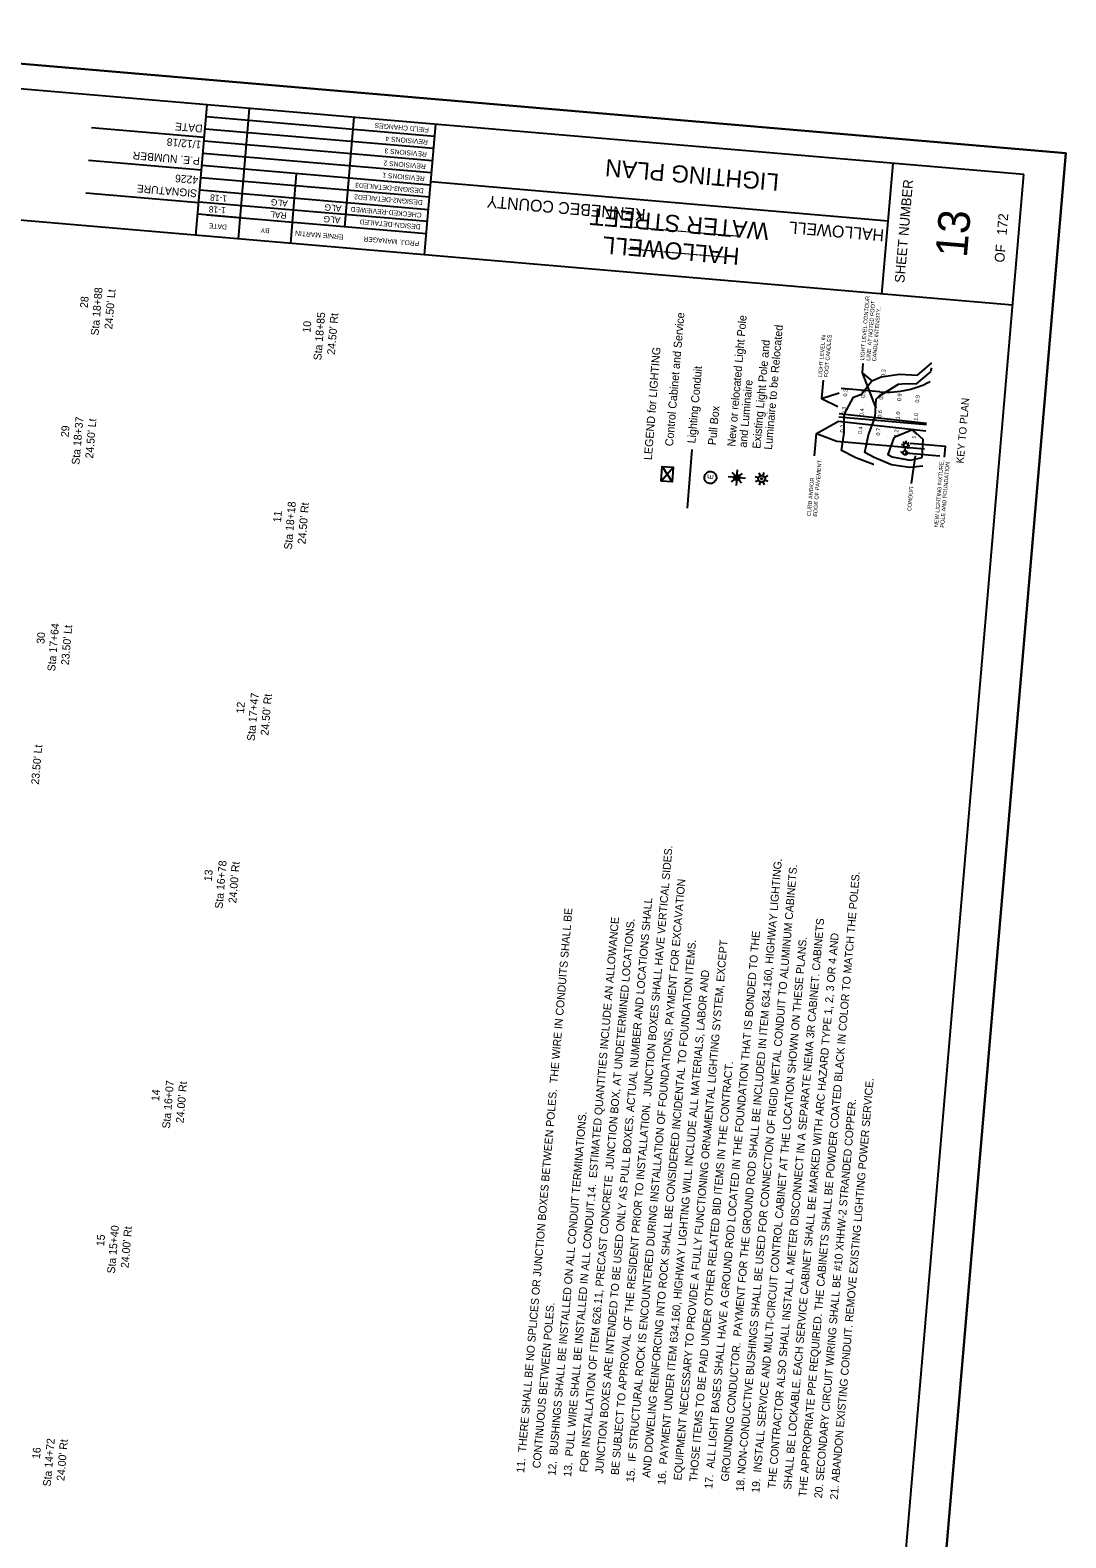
# Model space of a CAD drawing. Extents: x 1137099 to 1137719, y 529062 to 529956.
# Drawn here: x 1137324 to 1137719, y 529381 to 529956 of the extents above; entities that cross this region are included whole.
import ezdxf

# ---------------------------------------------------------------- set-up
doc = ezdxf.new("R2010")
doc.units = 0
for name, color, linetype in [('ANNOTATION', 7, 'Continuous'), ('BORDER', 7, 'Continuous'), ('BRIDGE_TITLE', 7, 'Continuous'), ('D_LIGHTING', 7, 'Continuous'), ('D_Lighting_Text', 7, 'Continuous'), ('D_Utilities_Pole_StreetLight', 7, 'Continuous'), ('HIGHWAY_TITLE', 7, 'Continuous'), ('Liting Text', 7, 'Continuous'), ('PLOT BOUNDARY', 7, 'Continuous'), ('UTILS GRND', 7, 'Continuous')]:
    doc.layers.add(name, color=color, linetype=linetype)

msp = doc.modelspace()

# ---------------------------------------------------------------- linework, layer by layer
at = {"layer": 'ANNOTATION'}
for p, q in [((1137641.47, 529825.05), (1137646.62, 529811.52)), ((1137625.94, 529815.24), (1137632.65, 529817.34)), ((1137648.23, 529817.78), (1137633.51, 529819.04)), ((1137665.97, 529805.2), (1137632.56, 529808.07)), ((1137666.01, 529805.64), (1137632.67, 529809.37)), ((1137632.44, 529806.62), (1137665.77, 529802.89)), ((1137624.04, 529801.85), (1137631.77, 529798.92)), ((1137631.77, 529798.92), (1137665.18, 529796.06)), ((1137656.55, 529797.67), (1137656.56, 529797.72)), ((1137659.29, 529797.44), (1137659.3, 529797.49)), ((1137656.31, 529794.93), (1137656.32, 529794.98)), ((1137657.45, 529794.06), (1137657.45, 529794.06)), ((1137657.48, 529794.41), (1137657.48, 529794.41)), ((1137657.79, 529794.03), (1137657.79, 529794.03)), ((1137657.82, 529794.38), (1137657.82, 529794.38)), ((1137660.28, 529782.77), (1137661.82, 529793.4))]:
    msp.add_line(p, q, dxfattribs=at)
msp.add_lwpolyline([(1137098.65, 529108.8), (1137171.14, 529955.71), (1137719.13, 529908.81), (1137646.65, 529061.9)], close=True, dxfattribs=at)
for points in [[(1137645.97, 529790.05), (1137645.76, 529790.1), (1137639.08, 529792.65), (1137633.62, 529795.36), (1137634.63, 529802.18), (1137634.63, 529809.09), (1137638.11, 529815.7), (1137641.17, 529816.85), (1137645.12, 529822.01), (1137648.66, 529823.51), (1137655.65, 529824.46), (1137662.53, 529824.12), (1137666.07, 529827.13), (1137668.01, 529828.76)], [(1137641.77, 529828.55), (1137641.47, 529825.05), (1137645.12, 529822.01)], [(1137664.6, 529789.47), (1137659.48, 529788.96), (1137652.65, 529789.89), (1137645.99, 529792.77), (1137642.55, 529794.59), (1137643.86, 529801.39), (1137646.4, 529808.08), (1137646.85, 529814.95), (1137648.03, 529816.26), (1137655.32, 529820.72), (1137658.05, 529820.9), (1137662.24, 529820.84), (1137667.73, 529825.49)], [(1137626.55, 529822.24), (1137625.94, 529815.24), (1137632.24, 529812.13)], [(1137623.3, 529793.37), (1137624.04, 529801.85), (1137632.44, 529806.62)], [(1137664.3, 529792.73), (1137664.79, 529799.59), (1137660.72, 529803.3), (1137653.92, 529800.53), (1137653.54, 529800.17), (1137651.23, 529793.85), (1137652.92, 529792.94), (1137659.72, 529791.68), (1137664.3, 529792.73)], [(1137672.86, 529792.83), (1137673.21, 529796.89), (1137659.75, 529798.04)]]:
    msp.add_lwpolyline(points, dxfattribs=at)
for centre, major_axis, start_param, end_param in [((1137669.03, 529826.16), (0.89, 1.05), 1.737973, 2.633498), ((1137651.2, 529852.08), (22.21, 26.32), 4.064294, 4.213502), ((1137651.2, 529852.08), (22.21, 26.32), 4.213502, 4.323837), ((1137651.2, 529852.08), (22.21, 26.32), 4.323837, 4.333024), ((1137651.2, 529852.08), (22.21, 26.32), 3.756531, 4.064294)]:
    msp.add_ellipse(centre, major_axis=major_axis, ratio=0.998974, start_param=start_param, end_param=end_param, dxfattribs=at)
at = {"layer": 'BORDER'}
for p, q in [((1137703.07, 529900.61), (1137179.98, 529945.38)), ((1137387.44, 529877.44), (1137391.7, 529927.26)), ((1137390.64, 529914.81), (1137347.56, 529918.49)), ((1137474.62, 529869.98), (1137478.89, 529919.8)), ((1137389.57, 529902.35), (1137346.49, 529906.04)), ((1137634.86, 529103.53), (1137703.08, 529900.61)), ((1137648.98, 529855.06), (1137653.25, 529904.88)), ((1137698.8, 529850.79), (1137175.72, 529895.56)), ((1137651.37, 529882.91), (1137477.01, 529897.83)), ((1137388.51, 529889.9), (1137345.43, 529893.58))]:
    msp.add_line(p, q, dxfattribs=at)
for points in [[(1137403.63, 529876.06), (1137407.9, 529925.88)], [(1137478.08, 529910.52), (1137390.91, 529917.98)], [(1137478.47, 529915.16), (1137391.31, 529922.62)], [(1137444.17, 529880.69), (1137447.75, 529922.46)], [(1137477.68, 529905.88), (1137390.51, 529913.34)], [(1137477.28, 529901.24), (1137390.12, 529908.7)], [(1137476.88, 529896.6), (1137389.72, 529904.06)], [(1137424.25, 529882.4), (1137425.84, 529900.96)], [(1137388.92, 529894.78), (1137476.09, 529887.32)], [(1137476.49, 529891.96), (1137389.32, 529899.42)], [(1137475.69, 529882.67), (1137388.53, 529890.13)], [(1137404.32, 529884.1), (1137388.13, 529885.49)], [(1137475.3, 529878.03), (1137391.65, 529885.19)], [(1137423.56, 529874.35), (1137424.25, 529882.4)]]:
    msp.add_lwpolyline(points, dxfattribs=at)
at = {"layer": 'D_LIGHTING'}
for p, q in [((1137564.85, 529783.68), (1137569.41, 529789.02)), ((1137565.2, 529789.29), (1137569.06, 529783.41)), ((1137593.68, 529785.04), (1137590.4, 529785.37)), ((1137593.68, 529785.04), (1137591.52, 529783.46)), ((1137593.68, 529785.04), (1137591.88, 529787.02)), ((1137593.68, 529785.04), (1137593.38, 529782.09)), ((1137593.68, 529785.04), (1137593.98, 529787.99)), ((1137593.68, 529785.04), (1137595.84, 529786.62)), ((1137596.96, 529784.7), (1137593.68, 529785.04)), ((1137593.68, 529785.04), (1137595.47, 529783.06)), ((1137600.73, 529785.45), (1137601.94, 529785.03)), ((1137602.04, 529786.91), (1137602.59, 529785.75)), ((1137604, 529787.01), (1137603.57, 529785.81)), ((1137605.46, 529785.7), (1137604.3, 529785.15)), ((1137600.83, 529783.5), (1137601.99, 529784.05)), ((1137602.29, 529782.19), (1137602.72, 529783.39)), ((1137604.25, 529782.29), (1137603.7, 529783.44)), ((1137604.35, 529784.17), (1137605.56, 529783.74))]:
    msp.add_line(p, q, dxfattribs=at)
msp.add_lwpolyline([(1137564.85, 529783.68), (1137565.2, 529789.29), (1137569.41, 529789.02), (1137569.06, 529783.41)], close=True, dxfattribs=at)
for radius in [1.28, 0.29]:
    msp.add_circle((1137603.15, 529784.6), radius, dxfattribs=at)
msp.add_ellipse((1137593.68, 529785.04), major_axis=(1.12, -0.11), ratio=0.899857, dxfattribs=at)
at = {"layer": 'D_Utilities_Pole_StreetLight'}
for p, q in [((1137657.32, 529797.52), (1137656.53, 529797.59)), ((1137657.5, 529796.93), (1137656.89, 529796.42)), ((1137657.61, 529798.06), (1137657.09, 529798.67)), ((1137657.93, 529795.34), (1137658.05, 529796.65)), ((1137658.19, 529798.24), (1137658.26, 529799.04)), ((1137658.63, 529796.83), (1137659.14, 529796.21)), ((1137658.73, 529797.96), (1137659.35, 529798.47)), ((1137658.92, 529797.37), (1137659.71, 529797.3)), ((1137657.04, 529794.6), (1137656.22, 529794.67)), ((1137658.67, 529794.45), (1137659.49, 529794.38))]:
    msp.add_line(p, q, dxfattribs=at)
for centre, major_axis in [((1137658.12, 529797.44), (-0.516, -0.612)), ((1137657.85, 529794.52), (0.529, 0.627))]:
    msp.add_ellipse(centre, major_axis=major_axis, ratio=0.998974, dxfattribs=at)
at = {"layer": 'Liting Text'}
for p, q in [((1137574.81, 529773.45), (1137576.71, 529795.73)), ((1137657.85, 529794.52), (1137671.07, 529793.39))]:
    msp.add_line(p, q, dxfattribs=at)
at = {"layer": 'PLOT BOUNDARY'}
msp.add_lwpolyline([(1137646.65, 529061.9), (1137719.13, 529908.81), (1137171.14, 529955.71), (1137098.65, 529108.8)], close=True, dxfattribs=at)
at = {"layer": 'UTILS GRND'}
msp.add_ellipse((1137583.58, 529785.08), major_axis=(-2.29, 0.32), ratio=0.999971, dxfattribs=at)

# ---------------------------------------------------------------- texts
at = {"layer": 'ANNOTATION'}
for s, height, rotation, p in [('LIGHT LEVEL CONTOUR', 1.528, 85.04728, (1137642.2, 529829.74)), ('LINE  AT NOTED FOOT', 1.528, 85.04728, (1137644.48, 529829.55)), ('CANDLE INTENSITY.', 1.528, 85.04728, (1137646.77, 529829.35)), ('LIGHT LEVEL IN', 1.528, 85.04728, (1137626.14, 529823.39)), ('FOOT CANDLES', 1.528, 85.04728, (1137628.42, 529823.2)), ('0.3', 1.528, 85.04728, (1137650.18, 529823.38)), ('0.3', 1.528, 85.04728, (1137635.72, 529815.91)), ('0.3', 1.528, 85.04728, (1137642.57, 529815.32)), ('0.6', 1.528, 85.04728, (1137649.43, 529814.73)), ('0.9', 1.528, 85.04728, (1137656.29, 529814.14)), ('0.9', 1.528, 85.04728, (1137663.15, 529813.56)), ('KEY TO PLAN', 2.8603, 85.04728, (1137680.17, 529790.35)), ('0.3', 1.528, 85.04728, (1137635.12, 529809.05)), ('0.4', 1.528, 85.04728, (1137641.98, 529808.46)), ('0.6', 1.528, 85.04728, (1137648.84, 529807.87)), ('1.0', 1.528, 85.04728, (1137655.69, 529807.28)), ('1.0', 1.528, 85.04728, (1137662.55, 529806.7)), ('0.3', 1.528, 85.04728, (1137634.53, 529802.19)), ('0.4', 1.528, 85.04728, (1137641.38, 529801.6)), ('0.7', 1.528, 85.04728, (1137648.24, 529801.01)), ('1.2', 1.528, 85.04728, (1137655.1, 529800.43)), ('1.4', 1.528, 85.04728, (1137661.96, 529799.84)), ('EDGE OF PAVEMENT.', 1.528, 85.04728, (1137624.19, 529770.08)), ('NEW LIGHTING FIXTURE,', 1.528, 85.04728, (1137670.41, 529766.12)), ('POLE AND FOUNDATION.', 1.528, 85.04728, (1137672.69, 529765.92)), ('CURB AND/OR', 1.528, 85.04728, (1137621.9, 529770.27)), ('CONDUIT', 1.528, 85.04728, (1137660.16, 529772.25)), ('  BE SUBJECT TO APPROVAL OF THE RESIDENT PRIOR TO INSTALLATION.  JUNCTION BOXES SHALL HAVE VERTICAL SIDES.', 3, 85.10821, (1137548.44, 529402.32)), ('   GROUNDING CONDUCTOR.  PAYMENT FOR THE GROUND ROD SHALL BE INCLUDED IN ITEM 634.160, HIGHWAY LIGHTING.', 3, 85.10821, (1137590.29, 529398.74)), ('18. NON-CONDUCTIVE BUSHINGS SHALL BE USED FOR CONNECTION OF RIGID METAL CONDUIT TO ALUMINUM CABINETS.', 3, 85.10821, (1137596.26, 529398.23)), ('15.  IF STRUCTURAL ROCK IS ENCOUNTERED DURING INSTALLATION OF FOUNDATIONS, PAYMENT FOR EXCAVATION ', 3, 85.10821, (1137554.42, 529401.81)), ('THE APPROPRIATE PPE REQUIRED. THE CABINETS SHALL BE POWDER COATED BLACK IN COLOR TO MATCH THE POLES.', 3, 85.10821, (1137620.18, 529396.18)), ('  JUNCTION BOXES ARE INTENDED TO BE USED ONLY AS PULL BOXES. ACTUAL NUMBER AND LOCATIONS SHALL ', 3, 85.10821, (1137542.46, 529402.83)), ('11.  THERE SHALL BE NO SPLICES OR JUNCTION BOXES BETWEEN POLES.  THE WIRE IN CONDUITS SHALL BE ', 3, 85.10821, (1137512.57, 529405.39)), ('13.  PULL WIRE SHALL BE INSTALLED IN ALL CONDUIT.14.  ESTIMATED QUANTITIES INCLUDE AN ALLOWANCE ', 3, 85.10821, (1137530.5, 529403.86)), ('  FOR INSTALLATION OF ITEM 626.11, PRECAST CONCRETE  JUNCTION BOX, AT UNDETERMINED LOCATIONS. ', 3, 85.10821, (1137536.48, 529403.34)), ('  THE CONTRACTOR ALSO SHALL INSTALL A METER DISCONNECT IN A SEPARATE NEMA 3R CABINET. CABINETS ', 3, 85.10821, (1137608.22, 529397.21)), ('  AND DOWELING REINFORCING INTO ROCK SHALL BE CONSIDERED INCIDENTAL TO FOUNDATION ITEMS.', 3, 85.10821, (1137560.39, 529401.3)), ('  EQUIPMENT NECESSARY TO PROVIDE A FULLY FUNCTIONING ORNAMENTAL LIGHTING SYSTEM, EXCEPT ', 3, 85.10821, (1137572.35, 529400.27)), ('17.  ALL LIGHT BASES SHALL HAVE A GROUND ROD LOCATED IN THE FOUNDATION THAT IS BONDED TO THE', 3, 85.10821, (1137584.31, 529399.25)), ('19.  INSTALL SERVICE AND MULTI-CIRCUIT CONTROL CABINET AT THE LOCATION SHOWN ON THESE PLANS.  ', 3, 85.10821, (1137602.24, 529397.72)), ('  SHALL BE LOCKABLE. EACH SERVICE CABINET SHALL BE MARKED WITH ARC HAZARD TYPE 1, 2, 3 OR 4 AND ', 3, 85.10821, (1137614.2, 529396.69)), ('16.  PAYMENT UNDER ITEM 634.160, HIGHWAY LIGHTING WILL INCLUDE ALL MATERIALS, LABOR AND ', 3, 85.10821, (1137566.37, 529400.79)), ('  THOSE ITEMS TO BE PAID UNDER OTHER RELATED BID ITEMS IN THE CONTRACT.', 3, 85.10821, (1137578.33, 529399.76)), ('21. ABANDON EXISTING CONDUIT. REMOVE EXISTING LIGHTING POWER SERVICE.', 3, 85.10821, (1137632.13, 529395.16)), ('20. SECONDARY CIRCUIT WIRING SHALL BE #10 XHHW-2 STRANDED COPPER.', 3, 85.10821, (1137626.15, 529395.67)), ('12.  BUSHINGS SHALL BE INSTALLED ON ALL CONDUIT TERMINATIONS.', 3, 85.10821, (1137524.53, 529404.37)), ('  CONTINUOUS BETWEEN POLES.  ', 3, 85.10821, (1137518.55, 529404.88))]:
    msp.add_text(s, height=height, rotation=rotation, dxfattribs=at).set_placement(p)
at = {"layer": 'BORDER'}
for s, height, rotation, p in [('DATE', 2.953, 175.10821, (1137390.08, 529919.58)), ('FIELD CHANGES', 1.8637, 175.10821, (1137476.33, 529918.53)), ('1/12/18', 2.953, 175.10821, (1137389.56, 529913.45)), ('REVISIONS 4', 1.8637, 175.10821, (1137475.93, 529913.89)), ('P.E. NUMBER', 2.9528, 175.10821, (1137389.03, 529907.22)), ('REVISIONS 2', 1.8637, 175.10821, (1137475.14, 529904.6)), ('REVISIONS 3', 1.8637, 175.10821, (1137475.53, 529909.24)), ('LIGHTING PLAN', 6.5214, 175.10821, (1137609.97, 529900.88)), ('4226', 2.953, 175.10821, (1137388.4, 529899.92)), ('REVISIONS 1', 1.8637, 175.10821, (1137474.74, 529899.96)), ('SIGNATURE', 2.953, 175.10821, (1137387.97, 529894.86)), ('DESIGN3-DETAILED3', 1.8637, 175.10821, (1137474.34, 529895.32)), ('SHEET NUMBER', 3.7264, 85.10821, (1137657.55, 529859.17)), ('1-18', 2.423, 175.10821, (1137398.9, 529888.12)), ('1-18', 2.423, 175.10821, (1137399.4, 529892.57)), ('ALG', 2.423, 175.10821, (1137422.53, 529890.77)), ('ALG', 2.423, 175.10821, (1137443, 529888.83)), ('CHECKED-REVIEWED', 1.8637, 175.10821, (1137473.55, 529886.04)), ('DESIGN2-DETAILED2', 1.8637, 175.10821, (1137473.96, 529890.86)), ('RAL', 2.423, 175.10821, (1137422.13, 529886.13)), ('ALG', 2.423, 175.10821, (1137442.62, 529884.38)), ('DESIGN-DETAILED', 1.8637, 175.10821, (1137473.17, 529881.58)), ('13', 12.097, 85.10821, (1137681.37, 529868.7)), ('172', 3.726, 85.10821, (1137696.51, 529877.37)), ('DATE', 1.857, 175.10821, (1137399.3, 529881.47)), ('BY', 1.857, 175.10821, (1137415.59, 529880.07)), ('ERNIE MARTIN', 1.8637, 175.10821, (1137443.71, 529877.67)), ('PROJ. MANAGER', 1.8637, 175.10821, (1137472.62, 529875.19)), ('OF', 3.726, 85.10821, (1137695.62, 529866.96))]:
    msp.add_text(s, height=height, rotation=rotation, dxfattribs=at).set_placement(p)
at = {"layer": 'BRIDGE_TITLE'}
for s, height, p in [('KENNEBEC COUNTY', 4.5358, (1137559.03, 529887.45)), ('HALLOWELL', 4.536, (1137649.98, 529879.66)), ('_____________', 4.5358, (1137594.63, 529875.99)), ('___________', 4.5358, (1137588.96, 529868.06))]:
    msp.add_text(s, height=height, rotation=175.10821, dxfattribs=at).set_placement(p)
at = {"layer": 'D_Lighting_Text'}
for s, p in [('28', (1137346.16, 529849.62)), ('Sta 18+88', (1137350.28, 529839.14)), ("24.50' Lt", (1137355.5, 529841.54)), ('Sta 18+85', (1137435.2, 529829.68)), ('10', (1137431.08, 529840.22)), ("24.50' Rt", (1137440.4, 529831.82)), ('Sta 18+37', (1137342.99, 529789.85)), ('29', (1137338.87, 529800.36)), ("24.50' Lt", (1137348.21, 529792.25)), ('Sta 18+18', (1137423.98, 529757.48)), ("24.50' Rt", (1137429.18, 529759.56)), ('11', (1137419.85, 529767.86)), ('Sta 17+64', (1137333.74, 529711.05)), ("23.50' Lt", (1137338.96, 529713.45)), ('30', (1137329.62, 529721.53)), ('12', (1137405.73, 529694.95)), ('Sta 17+47', (1137409.85, 529684.5)), ("24.50' Rt", (1137415.05, 529686.58)), ("23.50' Lt", (1137327.54, 529667.86)), ('13', (1137393.46, 529630.97)), ('Sta 16+78', (1137397.58, 529620.53)), ("24.00' Rt", (1137402.78, 529622.61)), ('Sta 16+07', (1137377.51, 529536.67)), ("24.00' Rt", (1137382.71, 529538.75)), ('14', (1137373.39, 529547.15)), ('Sta 15+40', (1137356.52, 529481.39)), ("24.00' Rt", (1137361.72, 529483.47)), ('15', (1137352.4, 529491.81)), ('Sta 14+72', (1137332.05, 529400.17)), ("24.00' Rt", (1137337.25, 529402.28)), ('16', (1137327.93, 529410.65))]:
    msp.add_text(s, height=3, rotation=85.10821, dxfattribs=at).set_placement(p)
at = {"layer": 'HIGHWAY_TITLE'}
for s, height, p in [('WATER STREET', 6.5214, (1137606.1, 529882.11)), ('HALLOWELL', 6.521, (1137594.91, 529872.6))]:
    msp.add_text(s, height=height, rotation=175.10821, dxfattribs=at).set_placement(p)
at = {"layer": 'Liting Text'}
for s, height, rotation, p in [('Control Cabinet and Service', 3.0627, 85.06516, (1137569.33, 529796.91)), ('New or relocated Light Pole', 3.0624, 84.96104, (1137593.02, 529796.79)), ('Luminaire to be Relocated', 3.0624, 84.96104, (1137607.06, 529795.58)), ('Existing Light Pole and', 3.0624, 84.96104, (1137602.64, 529795.97)), ('LEGEND for LIGHTING', 3.0624, 85.55224, (1137561.26, 529791.65)), ('Lighting Conduit', 3.0624, 84.96104, (1137577.84, 529798.01)), ('and Luminaire', 3.0624, 84.96104, (1137597.44, 529796.4)), ('Pull Box', 3.062, 84.56946, (1137585.68, 529797.3))]:
    msp.add_text(s, height=height, rotation=rotation, dxfattribs=at).set_placement(p)
at = {"layer": 'UTILS GRND'}
msp.add_text('E', height=2.12, rotation=85.14305, dxfattribs=at).set_placement((1137584.59, 529784.38))

doc.saveas('drawing.dxf')
